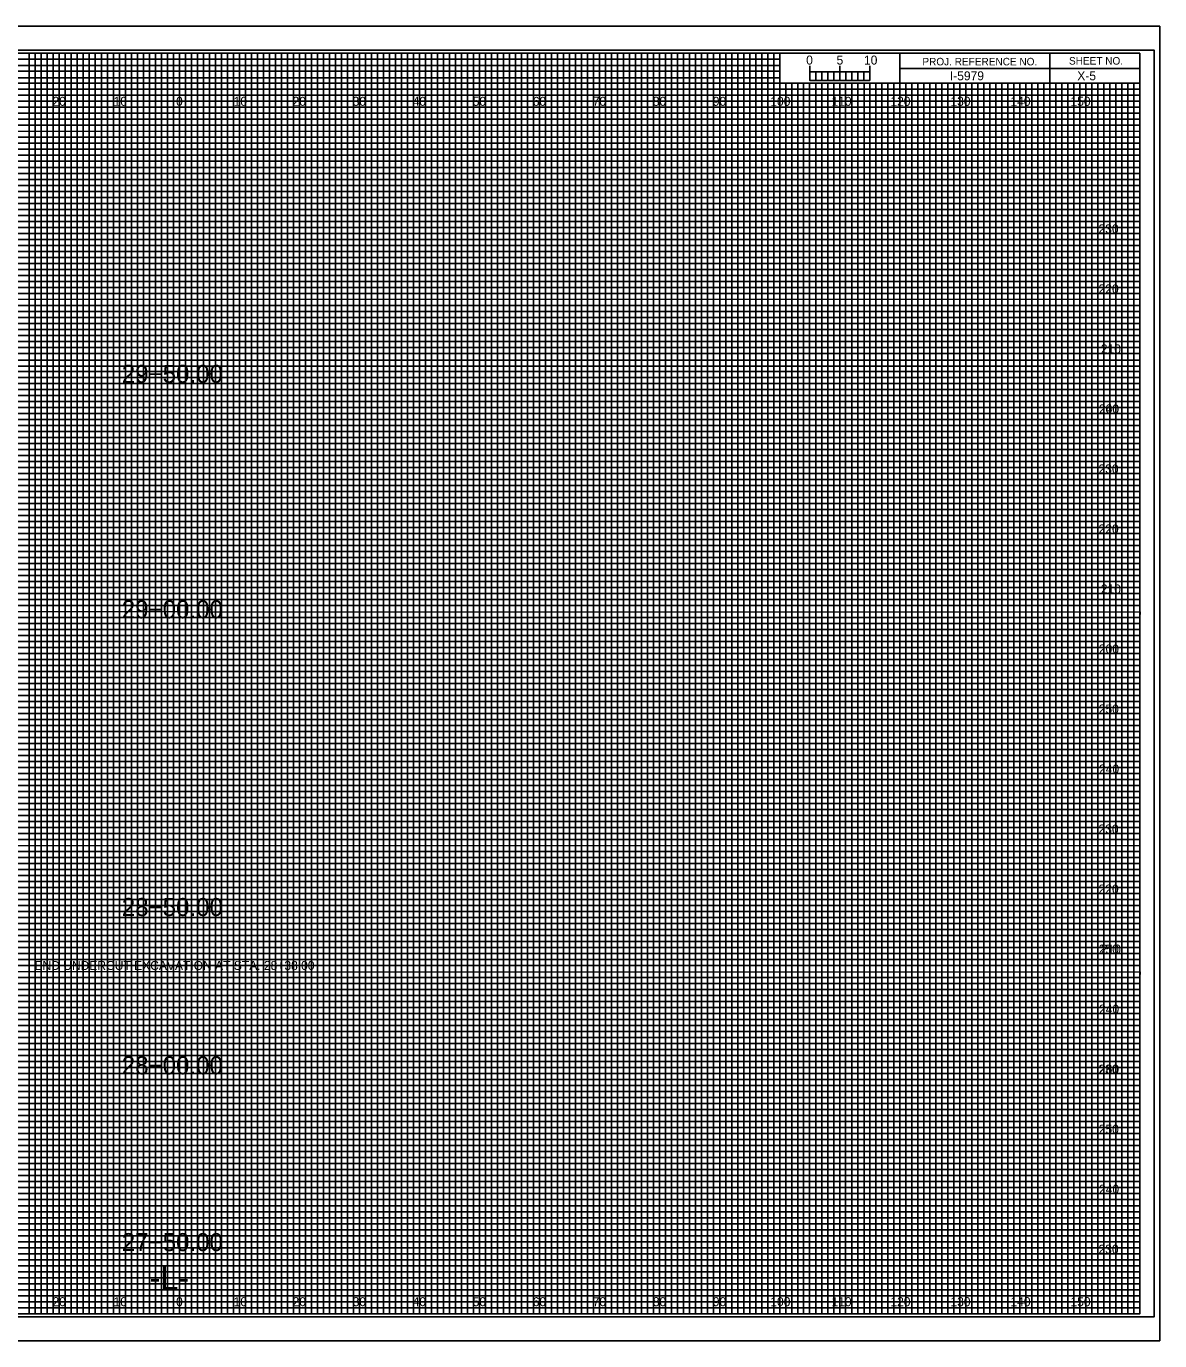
# Model space of a CAD drawing. Extents: x -13 to 359, y -5 to 2854.
# Drawn here: x 134.5 to 323.3, y 875.5 to 1094.5 of the extents above; entities that cross this region are included whole.
import ezdxf

# ---------------------------------------------------------------- set-up
doc = ezdxf.new("R2010")
doc.units = 0
for name, color, linetype in [('Exist CMT Pavement', 7, 'Continuous'), ('Exist Cross Section Cell', 7, 'Continuous'), ('Exist XS Ground Line', 7, 'Continuous'), ('Prop CMT Conc Surface', 7, 'Continuous'), ('Prop CMT Concrete Structures', 7, 'Continuous'), ('Prop CMT DNC', 7, 'Continuous'), ('Prop CMT Pvmt Course 1', 7, 'Continuous'), ('Prop CMT Pvmt Course 1 CG', 7, 'Continuous'), ('Prop CMT Pvmt Course 1 Wedge', 7, 'Continuous'), ('Prop CMT Pvmt Course 2', 7, 'Continuous'), ('Prop CMT Pvmt Course 2 Wedge', 7, 'Continuous'), ('Prop CMT Pvmt Course 3', 7, 'Continuous'), ('Prop CMT Pvmt Course 3 Wedge', 7, 'Continuous'), ('Prop CMT Pvmt Wedge Surface 2', 7, 'Continuous'), ('Prop CMT Shear Line', 7, 'Continuous'), ('Prop CMT Slope Grass', 7, 'Continuous'), ('Prop CMT Subgrade Earthwork', 7, 'Continuous'), ('Scratch_Level_0', 7, 'Continuous')]:
    doc.layers.add(name, color=color, linetype=linetype)

msp = doc.modelspace()

# ---------------------------------------------------------------- linework, layer by layer
at = {"layer": 'Exist XS Ground Line'}
for p, q in [((150, 1090), (140, 1090)), ((140, 1090), (140, 880)), ((150, 880), (150, 1090)), ((170, 1090), (160, 1090)), ((160, 1090), (160, 880)), ((170, 880), (170, 1090)), ((190, 1090), (180, 1090)), ((180, 1090), (180, 880)), ((190, 880), (190, 1090)), ((210, 1090), (200, 1090)), ((200, 1090), (200, 880)), ((210, 880), (210, 1090)), ((230, 1090), (220, 1090)), ((220, 1090), (220, 880)), ((230, 880), (230, 1090)), ((250, 1090), (240, 1090)), ((240, 1090), (240, 880)), ((250, 880), (250, 1090)), ((260, 1090), (260, 880)), ((270, 880), (270, 1085)), ((290, 1085), (280, 1085)), ((280, 1085), (280, 880)), ((290, 880), (290, 1085)), ((310, 1085), (300, 1085)), ((300, 1085), (300, 880)), ((310, 880), (310, 1085)), ((140, 880), (130, 880)), ((160, 880), (150, 880)), ((180, 880), (170, 880)), ((200, 880), (190, 880)), ((220, 880), (210, 880)), ((240, 880), (230, 880)), ((260, 880), (250, 880)), ((280, 880), (270, 880)), ((300, 880), (290, 880)), ((320, 880), (310, 880)), ((320, 880), (320, 880))]:
    msp.add_line(p, q, dxfattribs=at)
for points in [[(0, 1080), (320, 1080), (320, 1070), (0, 1070)], [(0, 1060), (320, 1060), (320, 1050), (0, 1050)], [(0, 1040), (320, 1040), (320, 1030), (0, 1030)], [(0, 1020), (320, 1020), (320, 1010), (0, 1010)], [(0, 1000), (320, 1000), (320, 990), (0, 990)], [(0, 980), (320, 980), (320, 970), (0, 970)], [(0, 960), (320, 960), (320, 950), (0, 950)], [(0, 940), (320, 940), (320, 930), (0, 930)], [(0, 920), (320, 920), (320, 910), (0, 910)], [(0, 900), (320, 900), (320, 890), (0, 890)]]:
    msp.add_lwpolyline(points, dxfattribs=at)
at = {"layer": 'Prop CMT Conc Surface'}
for p, q in [((265, 1085.49), (265, 1087.9)), ((265, 1086.9), (265, 1087.9)), ((270, 1085.49), (270, 1087.9)), ((275, 1085.49), (275, 1087.9)), ((275, 1086.9), (275, 1087.9))]:
    msp.add_line(p, q, dxfattribs=at)
for points in [[(275, 1086.9), (265, 1086.9), (265, 1085.49), (275, 1085.49)], [(265, 1086.9), (266, 1086.9), (266, 1085.49), (265, 1085.49)], [(267, 1086.9), (268, 1086.9), (268, 1085.49), (267, 1085.49)], [(269, 1086.9), (270, 1086.9), (270, 1085.49), (269, 1085.49)], [(271, 1086.9), (272, 1086.9), (272, 1085.49), (271, 1085.49)], [(273, 1086.9), (274, 1086.9), (274, 1085.49), (273, 1085.49)]]:
    msp.add_lwpolyline(points, close=True, dxfattribs=at)
at = {"layer": 'Prop CMT Concrete Structures'}
for p, q in [((305, 1090), (305, 1085)), ((305, 1085), (305, 1090)), ((280, 1087.5), (280, 1085)), ((320, 1087.49), (280, 1087.49)), ((280, 1085), (320, 1085))]:
    msp.add_line(p, q, dxfattribs=at)
for points in [[(320, 1090), (0, 1090), (0, 880), (320, 880)], [(280, 1090), (260, 1090), (260, 1085.03), (280, 1085.03)], [(320, 1090), (280, 1090), (280, 1085), (320, 1085)]]:
    msp.add_lwpolyline(points, close=True, dxfattribs=at)
at = {"layer": 'Prop CMT DNC'}
for p, q in [((323.3, 1094.5), (-13.4, 1094.5)), ((-13.4, 875.5), (323.3, 875.5))]:
    msp.add_line(p, q, dxfattribs=at)
at = {"layer": 'Prop CMT Pvmt Course 1'}
for p, q in [((0, 1089), (260, 1089)), ((260, 1089), (260, 1087.98)), ((260, 1087.98), (0, 1087.98)), ((0, 1087), (260, 1087)), ((260, 1087), (260, 1085.89)), ((260, 1085.89), (0, 1085.89)), ((0, 1084), (320, 1084))]:
    msp.add_line(p, q, dxfattribs=at)
for points in [[(0, 1083), (270, 1083), (320, 1083), (320, 1082), (0, 1082)], [(0, 1081), (320, 1081), (320, 1079), (0, 1079)], [(0, 1078), (320, 1078), (320, 1077), (0, 1076.98)], [(0, 1076), (320, 1076), (320, 1074), (0, 1074)], [(0, 1073), (320, 1073), (320, 1072), (0, 1072)], [(0, 1071), (320, 1071), (320, 1069), (0, 1069)], [(0, 1068), (320, 1068), (320, 1067), (0, 1067)], [(0, 1066), (320, 1066), (320, 1064), (0, 1064)], [(0, 1063), (320, 1063), (320, 1062), (0, 1062)], [(0, 1061), (320, 1061), (320, 1059), (0, 1059)], [(0, 1058), (320, 1058), (320, 1057), (0, 1057)], [(0, 1056), (320, 1056), (320, 1053.95), (320, 1053), (320, 1052), (0, 1052)], [(0, 1054), (320, 1054), (320, 1053), (0, 1053)], [(0, 1051), (320, 1051), (320, 1049), (0, 1049.03)], [(0, 1049.03), (320, 1049), (320, 1048), (0, 1048)], [(0, 1047), (320, 1047), (320, 1046), (0, 1046)], [(0, 1044), (320, 1044), (320, 1043), (0, 1043)], [(0, 1042), (320, 1042), (320, 1041), (0, 1041)], [(-0.07, 1038.89), (320, 1038.89), (320, 1037.88), (-0.07, 1037.88)], [(0, 1037), (320, 1037), (320, 1036), (0, 1036)], [(0, 1034), (320, 1034), (320, 1033), (0, 1033)], [(0, 1032), (320, 1032), (320, 1031), (0, 1031)], [(0, 1029), (320, 1029), (320, 1028), (0, 1028)], [(0, 1027), (320, 1027), (320, 1026), (0, 1026)], [(0, 1024), (320, 1024), (320, 1023), (0, 1023)], [(0, 1022), (320, 1022), (320, 1021), (0, 1021)], [(0, 1019), (320, 1019), (319.99, 1017.98), (0, 1018)], [(0, 1017), (320, 1017), (320, 1016), (0, 1016)], [(0, 1014), (320, 1014), (320, 1013), (0, 1013)], [(0, 1012), (320, 1012), (320, 1011), (0, 1011)], [(0, 1009), (320, 1009), (320, 1008), (0, 1008)], [(0, 1007), (320, 1007), (320, 1006), (0, 1006)], [(0, 1004), (320, 1004), (320, 1003), (0, 1003)], [(0, 1002), (320, 1002), (320, 1001), (0, 1001)], [(0, 999), (320, 999), (320, 998), (0, 998)], [(0, 996.99), (320.07, 996.91), (320, 996), (0, 996)], [(0, 994), (320, 994), (320, 993), (0, 993)], [(0, 992), (320, 992), (320, 991), (0, 991)], [(0, 989), (320, 989), (320, 988), (0, 988)], [(0, 987), (320, 987), (320, 986), (0, 986)], [(0, 984), (320, 984), (320, 983), (0, 983)], [(0, 982), (320, 982), (320, 981), (0, 981)], [(0, 979), (320, 979), (320, 978), (0, 978)], [(0, 977), (320, 977), (320, 976), (0, 976)], [(0, 974), (320, 974), (320, 973), (0, 973)], [(0, 972), (320, 972), (320, 971), (0, 971)], [(0, 969), (320, 969), (320, 968), (0, 968)], [(0, 967), (320, 967), (320, 966), (0, 966)], [(0, 964), (320, 964), (320, 963), (0, 963)], [(0, 962), (320, 962), (320, 961), (0, 961)], [(0, 959), (320, 959), (319.99, 957.98), (0, 958)], [(0, 957), (320, 957), (320, 956), (0, 956)], [(0, 954), (320, 954), (320, 953), (0, 953)], [(0, 952), (320, 952), (320, 951), (0, 951)], [(0, 949), (320, 949), (320, 948), (0, 948)], [(0, 947), (320, 947), (320, 946), (0, 946)], [(0, 944), (320, 944), (320, 943), (0, 943)], [(0, 942), (320, 942), (320, 941), (0, 941)], [(0, 939), (320, 939), (320, 938), (0, 938)], [(0, 936.99), (320.07, 936.91), (320, 936), (0, 936)], [(0, 934), (320, 934), (320, 933), (0, 933)], [(0, 932), (320, 932), (320, 931), (0, 931)], [(0, 929), (320, 929), (320, 928), (0, 928)], [(0, 927), (320, 927), (320, 926), (0, 926)], [(0, 924), (320, 924), (320, 923), (0, 923)], [(0, 922), (320, 922), (320, 921), (0, 921)], [(0, 919), (320, 919), (320, 918), (0, 918)], [(0, 917), (320, 917), (320, 916), (0, 916)], [(0, 914), (320, 914), (320, 913), (0, 913)], [(0, 912), (320, 912), (320, 911), (0, 911)], [(0, 909), (320, 909), (320, 908), (0, 908)], [(0, 907), (320, 907), (320, 906), (0, 906)], [(0, 904), (320, 904), (320, 903), (0, 903)], [(0, 902), (320, 902), (320, 901), (0, 901)], [(0, 899), (320, 899), (320, 898), (0, 898)], [(0, 897), (320, 897), (320, 896), (0, 896)], [(0, 894), (320, 894), (320, 893), (0, 893)], [(0, 892), (320, 892), (320, 891), (0, 891)], [(0, 889), (320, 889), (320, 888), (0, 888)], [(0, 887), (320, 887), (320, 886), (0, 886)], [(0, 884), (320, 884), (320, 883), (0, 883)], [(0, 882), (320, 882), (320, 881), (0, 881)]]:
    msp.add_lwpolyline(points, dxfattribs=at)
at = {"layer": 'Prop CMT Pvmt Course 1 CG'}
for p, q in [((267, 1085), (266.01, 1085)), ((266.01, 1085), (266.01, 880)), ((267, 880), (267, 1085)), ((269, 1085), (268, 1085)), ((268, 1085), (268, 880)), ((269, 880), (269, 1085)), ((266.01, 880), (265, 880)), ((268, 880), (267, 880))]:
    msp.add_line(p, q, dxfattribs=at)
for points in [[(135, 880), (136, 880), (136, 1090), (137, 1090), (137, 880)], [(137, 880), (138, 880), (138, 1090), (139, 1090), (139, 880)], [(140, 880), (141, 880), (141, 1090), (142, 1090), (142, 880)], [(142, 880), (143, 880), (143, 1090), (144, 1090), (144, 880)], [(145, 880), (146, 880), (146, 1090), (147, 1090), (147, 880)], [(147, 880), (148, 880), (148, 1090), (149, 1090), (149, 880)], [(150, 880), (151, 880), (151, 1090), (152, 1090), (152, 880)], [(152, 880), (153, 880), (153, 1090), (154, 1090), (154, 880)], [(155, 880), (156, 880), (156, 1090), (157, 1090), (157, 880)], [(157, 880), (158, 880), (158, 1090), (159, 1090), (159, 880)], [(160, 880), (161, 880), (161, 1090), (162, 1090), (162, 880)], [(162, 880), (163, 880), (163, 1090), (164, 1090), (164, 880)], [(165, 880), (166, 880), (166, 1090), (167, 1090), (167, 880)], [(167, 880), (168, 880), (168, 1090), (169, 1090), (169, 880)], [(170, 880), (171, 880), (171, 1090), (172, 1090), (172, 880)], [(172, 880), (173, 880), (173, 1090), (174, 1090), (174, 880)], [(175, 880), (176, 880), (176, 1090), (177, 1090), (177, 880)], [(177, 880), (178, 880), (178, 1090), (179, 1090), (179, 880)], [(180, 880), (181, 880), (181, 1090), (182, 1090), (182, 880)], [(182, 880), (183, 880), (183, 1090), (184, 1090), (184, 880)], [(185, 880), (186, 880), (186, 1090), (187, 1090), (187, 880)], [(187, 880), (188, 880), (188, 1090), (189, 1090), (189, 880)], [(190, 880), (191, 880), (191, 1090), (192, 1090), (192, 880)], [(192, 880), (193, 880), (193, 1090), (194, 1090), (194, 880)], [(195, 880), (196, 880), (196, 1090), (197, 1090), (197, 880)], [(197, 880), (198, 880), (198, 1090), (199, 1090), (199, 880)], [(200, 880), (201, 880), (201, 1090), (202, 1090), (202, 880)], [(202, 880), (203, 880), (203, 1090), (204, 1090), (204, 880)], [(205, 880), (206, 880), (206, 1090), (207, 1090), (207, 880)], [(207, 880), (208, 880), (208, 1090), (209, 1090), (209, 880)], [(210, 880), (211, 880), (211, 1090), (212, 1090), (212, 880)], [(212, 880), (213, 880), (213, 1090), (214, 1090), (214, 880)], [(215, 880), (216, 880), (216, 1090), (217, 1090), (217, 880)], [(217, 880), (218, 880), (218, 1090), (219, 1090), (219, 880)], [(220, 880), (221, 880), (221, 1090), (222, 1090), (222, 880)], [(222, 880), (223, 880), (223, 1090), (224, 1090), (224, 880)], [(225, 880), (226, 880), (226, 1090), (227, 1090), (227, 880)], [(227, 880), (228, 880), (228, 1090), (229, 1090), (229, 880)], [(230, 880), (231, 880), (231, 1090), (232, 1090), (232, 880)], [(232, 880), (233, 880), (233, 1090), (234, 1090), (234, 880)], [(235, 880), (236, 880), (236, 1090), (237, 1090), (237, 880)], [(237, 880), (238, 880), (238, 1090), (239, 1090), (239, 880)], [(240, 880), (241, 880), (241, 1090), (242, 1090), (242, 880)], [(242, 880), (243, 880), (243, 1090), (244, 1090), (244, 880)], [(245, 880), (246, 880), (246, 1090), (247, 1090), (247, 880)], [(247, 880), (248, 880), (248, 1090), (249, 1090), (249, 880)], [(250, 880), (251, 880), (251, 1090), (252, 1090), (252, 880)], [(252, 880), (253, 880), (253, 1090), (254, 1090), (254, 880)], [(255, 880), (256, 880), (256, 1090), (257, 1090), (257, 880)], [(257, 880), (258, 880), (258, 1090), (259, 1090), (259, 880)], [(260, 880), (261, 880), (261, 1085), (262.02, 1085), (262.02, 880)], [(262, 880), (263, 880), (263, 1085), (263.99, 1085), (263.99, 880)], [(270, 880), (270.98, 880), (270.98, 1085), (272, 1085), (272, 880)], [(272, 880), (273, 880), (273, 1085), (274.05, 1085), (274.05, 880)], [(275, 880), (276, 880), (276, 1085), (277, 1085), (277, 880)], [(277, 880), (278, 880), (278, 1085), (279, 1085), (279, 880)], [(280, 880), (281, 880), (281, 1085), (282, 1085), (282, 880)], [(282, 880), (283, 880), (283, 1085), (284, 1085), (284, 880)], [(285, 880), (286, 880), (286, 1085), (287, 1085), (287, 880)], [(287, 880), (288, 880), (288, 1085), (289, 1085), (289, 880)], [(290, 880), (291, 880), (291, 1085), (292, 1085), (292, 880)], [(292, 880), (293, 880), (293, 1085), (294, 1085), (294, 880)], [(295, 880), (296, 880), (296, 1085), (297, 1085), (297, 880)], [(297, 880), (298, 880), (298, 1085), (299, 1085), (299, 880)], [(300, 880), (301, 880), (301, 1085), (302, 1085), (302, 880)], [(302, 880), (303, 880), (303, 1085), (304, 1085), (304, 880)], [(305, 880), (306, 880), (306, 1085), (307, 1085), (307, 880)], [(307, 880), (308, 880), (308, 1085), (309, 1085), (309, 880)], [(310, 880), (311, 880), (311, 1085), (312, 1085), (312, 880)], [(312, 880), (313, 880), (313, 1085), (314, 1085), (314, 880)], [(315, 880), (316, 880), (316, 1085), (317, 1085), (317, 880)], [(317, 880), (318, 880), (318, 1085), (319, 1085), (319, 880)]]:
    msp.add_lwpolyline(points, dxfattribs=at)
at = {"layer": 'Prop CMT Shear Line'}
for p, q in [((140, 880), (140, 1090)), ((150, 880), (150, 1090)), ((160, 880), (160, 1090)), ((170, 880), (170, 1090)), ((180, 880), (180, 1090)), ((190, 880), (190, 1090)), ((200, 880), (200, 1090)), ((210, 880), (210, 1090)), ((220, 880), (220, 1090)), ((230, 880), (230, 1090)), ((240, 880), (240, 1090)), ((250, 880), (250, 1090)), ((260, 880), (260, 1084.69)), ((270, 880), (270, 1084.69)), ((280, 880), (280, 1084.69)), ((290, 880), (290, 1084.69)), ((300, 880), (300, 1084.69)), ((310, 880), (310, 1084.69)), ((0, 1080), (320, 1080)), ((0, 1070), (320, 1070)), ((0, 1060), (320, 1060)), ((0, 1050), (320, 1050)), ((0, 1040), (320, 1040)), ((0, 1030), (320, 1030)), ((0, 1020), (320, 1020)), ((0, 1010), (320, 1010)), ((0, 1000), (320, 1000)), ((0, 990), (320, 990)), ((0, 980), (320, 980)), ((0, 970), (320, 970)), ((0, 960), (320, 960)), ((0, 950), (320, 950)), ((0, 940), (320, 940)), ((0, 930), (320, 930)), ((0, 920), (320, 920)), ((0, 910), (320, 910)), ((0, 900), (320, 900)), ((0, 890), (320, 890))]:
    msp.add_line(p, q, dxfattribs=at)
at = {"layer": 'Prop CMT Slope Grass'}
msp.add_lwpolyline([(-10.8, 879.5), (322.4, 879.5), (322.4, 1090.5), (-10.8, 1090.5)], close=True, dxfattribs=at)
at = {"layer": 'Prop CMT Subgrade Earthwork'}
msp.add_lwpolyline([(-13.4, 875.5), (323.3, 875.5), (323.3, 1094.5), (-13.4, 1094.5)], close=True, dxfattribs=at)
at = {"layer": 'Scratch_Level_0'}
for points in [[(125, 880), (135, 880), (135, 1090), (145, 1090), (145, 880), (155, 880), (155, 1090), (165, 1090), (165, 880), (175, 880), (175, 1090), (185, 1090), (185, 880), (195, 880), (195, 1090), (205, 1090), (205, 880), (215, 880), (215, 1090), (225, 1090), (225, 880), (235, 880), (235, 1090), (245, 1090), (245, 880), (255, 880), (255, 1090), (259.93, 1090), (260, 1090), (260, 1085), (264.99, 1085), (264.99, 880), (275, 880), (275, 1085), (285, 1085), (285, 880), (295, 880), (295, 1085), (305, 1085), (305, 880), (315, 880), (315, 1085)], [(0, 1085), (275, 1085)], [(0, 1065), (320, 1065), (320, 1075), (0, 1075)], [(0, 1045), (320, 1045), (320, 1055), (0, 1055)], [(0, 1025), (320, 1025), (320, 1035), (0, 1035)], [(0, 1005), (320, 1005), (320, 1015), (0, 1015)], [(0, 985), (320, 985), (320, 995), (0, 995)], [(0, 965), (320, 965), (320, 975), (0, 975)], [(0, 945), (320, 945), (320, 955), (0, 955)], [(0, 925), (320, 925), (320, 935), (0, 935)], [(0, 905), (320, 905), (320, 915), (0, 915)], [(0, 885), (320, 885), (320, 895), (0, 895)]]:
    msp.add_lwpolyline(points, dxfattribs=at)

# ---------------------------------------------------------------- texts
at = {"layer": 'Exist CMT Pavement'}
for s, p in [('5', (269.47, 1088.12)), ('10', (274.04, 1088.12))]:
    msp.add_text(s, height=1.5, dxfattribs=at).set_placement(p)
at = {"layer": 'Exist Cross Section Cell'}
for s, p in [('20', (138.86, 1081.25)), ('10', (149.04, 1081.25)), ('0', (159.45, 1081.25)), ('0', (159.45, 1081.25)), ('10', (169.04, 1081.25)), ('20', (178.86, 1081.25)), ('30', (188.86, 1081.25)), ('40', (198.86, 1081.25)), ('50', (208.86, 1081.25)), ('60', (218.86, 1081.25)), ('70', (228.86, 1081.25)), ('80', (238.86, 1081.25)), ('90', (248.86, 1081.25)), ('100', (258.44, 1081.25)), ('110', (268.62, 1081.25)), ('120', (278.44, 1081.25)), ('130', (288.44, 1081.25)), ('140', (298.44, 1081.25)), ('150', (308.44, 1081.25)), ('20', (138.86, 881.25)), ('10', (149.04, 881.25)), ('0', (159.45, 881.25)), ('0', (159.45, 881.25)), ('10', (169.04, 881.25)), ('20', (178.86, 881.25)), ('30', (188.86, 881.25)), ('40', (198.86, 881.25)), ('50', (208.86, 881.25)), ('60', (218.86, 881.25)), ('70', (228.86, 881.25)), ('80', (238.86, 881.25)), ('90', (248.86, 881.25)), ('100', (258.44, 881.25)), ('110', (268.62, 881.25)), ('120', (278.44, 881.25)), ('130', (288.44, 881.25)), ('140', (298.44, 881.25)), ('150', (308.44, 881.25))]:
    msp.add_text(s, height=1.5, dxfattribs=at).set_placement(p)
at = {"layer": 'Prop CMT Conc Surface'}
msp.add_text('0', height=1.5, dxfattribs=at).set_placement((264.41, 1088.12))
at = {"layer": 'Prop CMT Concrete Structures'}
for s, p in [('PROJ. REFERENCE NO.', (283.77, 1087.99)), ('SHEET NO.', (308.19, 1088.12))]:
    msp.add_text(s, height=1.25, dxfattribs=at).set_placement(p)
at = {"layer": 'Prop CMT Pvmt Course 1 Wedge'}
msp.add_text('X-5', height=1.5, dxfattribs=at).set_placement((309.57, 1085.5))
at = {"layer": 'Prop CMT Pvmt Course 2'}
for s, p in [('230', (313.11, 1060)), ('220', (313.12, 1050)), ('210', (313.5, 1040)), ('200', (313.17, 1030)), ('240', (313.19, 1030)), ('230', (313.11, 1020)), ('220', (313.12, 1010)), ('210', (313.5, 1000)), ('200', (313.17, 990)), ('250', (313.15, 980)), ('240', (313.19, 970)), ('230', (313.11, 960)), ('220', (313.12, 950)), ('250', (313.15, 940)), ('210', (313.5, 940)), ('240', (313.19, 930)), ('230', (313.11, 920)), ('260', (313.19, 920)), ('250', (313.15, 910)), ('240', (313.19, 900)), ('230', (313.11, 890))]:
    msp.add_text(s, height=1.5, dxfattribs=at).set_placement(p)
at = {"layer": 'Prop CMT Pvmt Course 2 Wedge'}
msp.add_text('I-5979', height=1.5, dxfattribs=at).set_placement((288.34, 1085.5))
at = {"layer": 'Prop CMT Pvmt Course 3'}
for s, p in [('29+50.00', (150.41, 1035.09)), ('29+00.00', (150.41, 995.86)), ('28+50.00', (150.41, 946.26)), ('28+00.00', (150.41, 919.88)), ('27+50.00', (150.41, 890.43))]:
    msp.add_text(s, height=3, dxfattribs=at).set_placement(p)
at = {"layer": 'Prop CMT Pvmt Course 3 Wedge'}
msp.add_text('-L-', height=4, dxfattribs=at).set_placement((155.06, 884))
at = {"layer": 'Prop CMT Pvmt Wedge Surface 2'}
msp.add_text('END UNDERCUT EXCAVATION AT STA. 28+38.00', height=1.5, rotation=360, dxfattribs=at).set_placement((135.86, 937.27))

doc.saveas('drawing.dxf')
